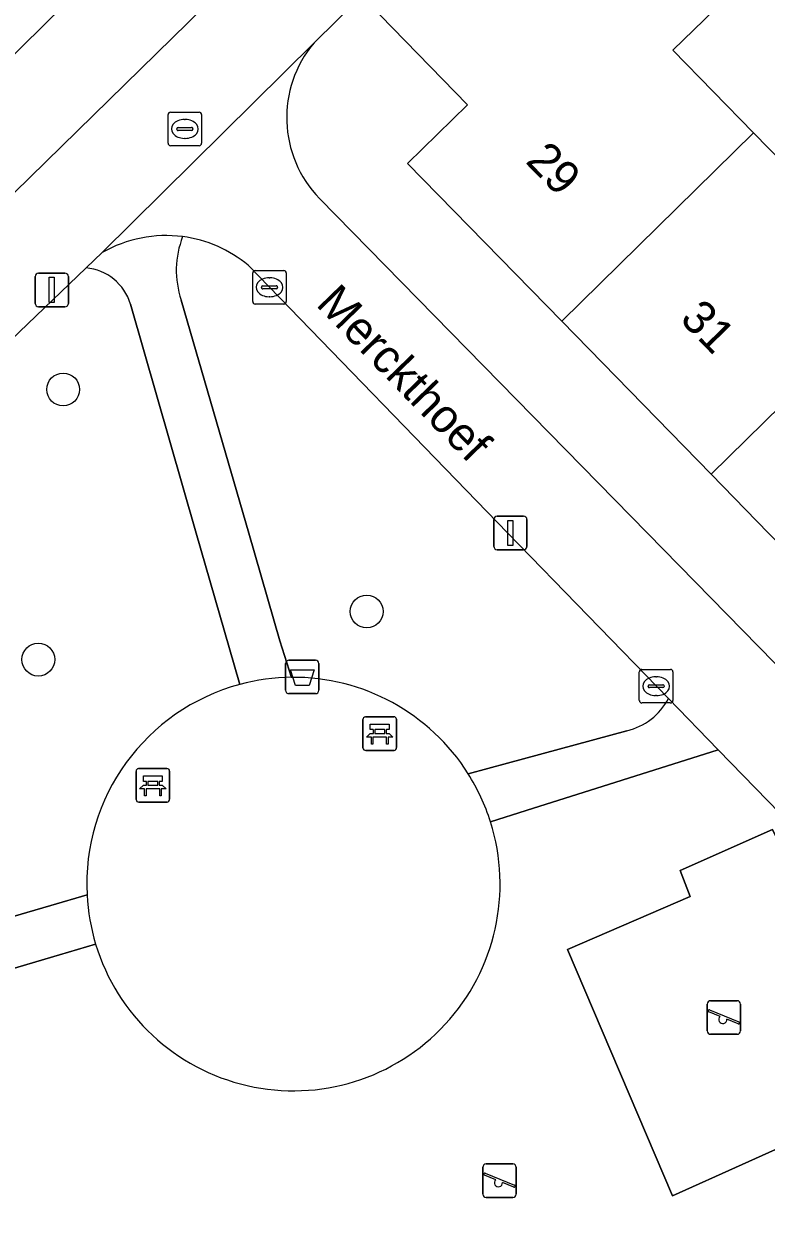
# Model space of a CAD drawing. Extents: x 162879 to 165540, y 384011 to 385181.
# Drawn here: x 164079.05 to 164101.17, y 384229.44 to 384265.17 of the extents above; entities that cross this region are included whole.
import ezdxf

# ---------------------------------------------------------------- set-up
doc = ezdxf.new("R2010")
doc.units = 0
for name, color, linetype in [('IMGEO_Afvalbak', 7, 'Continuous'), ('IMGEO_Bank', 7, 'Continuous'), ('IMGEO_Boom', 7, 'Continuous'), ('IMGEO_Erf', 7, 'Continuous'), ('IMGEO_Groenvoorziening', 7, 'Continuous'), ('IMGEO_Kolk', 7, 'Continuous'), ('IMGEO_Lichtmast', 7, 'Continuous'), ('IMGEO_Openbare_ruimte_label', 7, 'Continuous'), ('IMGEO_Pand', 7, 'Continuous'), ('IMGEO_Pand_nummerreeks', 7, 'Continuous'), ('IMGEO_Rioolput', 7, 'Continuous'), ('IMGEO_Speelvoorziening', 7, 'Continuous'), ('IMGEO_Terreindeel_zand', 7, 'Continuous'), ('IMGEO_Voetpad_halfverhard', 7, 'Continuous'), ('IMGEO_Voetpad_open', 7, 'Continuous')]:
    doc.layers.add(name, color=color, linetype=linetype)

msp = doc.modelspace()

# ---------------------------------------------------------------- linework, layer by layer
at = {"layer": 'IMGEO_Afvalbak'}
for p, q in [((164086.948, 384246.215), (164087.738, 384246.215)), ((164087.738, 384246.215), (164086.948, 384246.215)), ((164086.848, 384245.315), (164086.848, 384246.115)), ((164086.848, 384246.115), (164086.848, 384245.315)), ((164087.838, 384246.115), (164087.838, 384245.315)), ((164087.838, 384245.315), (164087.838, 384246.115)), ((164087.738, 384245.215), (164086.948, 384245.215)), ((164086.948, 384245.215), (164087.738, 384245.215))]:
    msp.add_line(p, q, dxfattribs=at)
msp.add_lwpolyline([(164086.991, 384245.929), (164087.695, 384245.929), (164087.546, 384245.459), (164087.14, 384245.459), (164086.991, 384245.929)], dxfattribs=at)
for centre, start, end in [((164086.948, 384246.115), 90, 180), ((164086.948, 384246.115), 90, 180), ((164087.738, 384246.115), 0, 90), ((164087.738, 384246.115), 360, 90), ((164086.948, 384245.315), 180, 270), ((164086.948, 384245.315), 180, 270), ((164087.738, 384245.315), 270, 0), ((164087.738, 384245.315), 270, 0)]:
    msp.add_arc(centre, 0.1, start, end, dxfattribs=at)
at = {"layer": 'IMGEO_Bank'}
for p, q in [((164089.154, 384243.6), (164089.154, 384244.441)), ((164089.154, 384244.441), (164089.154, 384243.6)), ((164089.229, 384244.525), (164090.07, 384244.525)), ((164090.07, 384244.525), (164089.229, 384244.525)), ((164090.154, 384244.45), (164090.154, 384243.609)), ((164090.154, 384243.609), (164090.154, 384244.45)), ((164089.463, 384244.031), (164089.463, 384244.137)), ((164089.507, 384244.137), (164089.507, 384244.031)), ((164089.795, 384244.143), (164089.513, 384244.143)), ((164089.513, 384244.025), (164089.795, 384244.025)), ((164089.801, 384244.031), (164089.801, 384244.137)), ((164089.845, 384244.137), (164089.845, 384244.031)), ((164089.851, 384243.923), (164089.458, 384243.923)), ((164090.079, 384243.525), (164089.238, 384243.525)), ((164089.238, 384243.525), (164090.079, 384243.525)), ((164082.466, 384242.984), (164083.307, 384242.984)), ((164083.307, 384242.984), (164082.466, 384242.984)), ((164083.391, 384242.909), (164083.391, 384242.068)), ((164083.391, 384242.068), (164083.391, 384242.909)), ((164082.391, 384242.059), (164082.391, 384242.9)), ((164082.391, 384242.9), (164082.391, 384242.059)), ((164082.7, 384242.49), (164082.7, 384242.596)), ((164082.744, 384242.596), (164082.744, 384242.49)), ((164083.032, 384242.602), (164082.75, 384242.602)), ((164083.038, 384242.49), (164083.038, 384242.596)), ((164083.082, 384242.596), (164083.082, 384242.49)), ((164083.088, 384242.382), (164082.695, 384242.382)), ((164082.75, 384242.484), (164083.032, 384242.484)), ((164083.316, 384241.984), (164082.475, 384241.984)), ((164082.475, 384241.984), (164083.316, 384241.984))]:
    msp.add_line(p, q, dxfattribs=at)
for points in [[(164089.401, 384243.923), (164089.259, 384243.923), (164089.371, 384244.025), (164089.457, 384244.025)], [(164089.457, 384244.143), (164089.371, 384244.143), (164089.371, 384244.304), (164089.934, 384244.304), (164089.934, 384244.143), (164089.851, 384244.143)], [(164089.851, 384244.025), (164089.934, 384244.025), (164090.046, 384243.923), (164089.907, 384243.923)], [(164089.451, 384243.916), (164089.451, 384243.709), (164089.408, 384243.709), (164089.408, 384243.916)], [(164089.901, 384243.916), (164089.901, 384243.709), (164089.857, 384243.709), (164089.857, 384243.916)], [(164082.694, 384242.602), (164082.608, 384242.602), (164082.608, 384242.763), (164083.171, 384242.763), (164083.171, 384242.602), (164083.088, 384242.602)], [(164082.638, 384242.382), (164082.496, 384242.382), (164082.608, 384242.484), (164082.694, 384242.484)], [(164082.688, 384242.375), (164082.688, 384242.168), (164082.645, 384242.168), (164082.645, 384242.375)], [(164083.088, 384242.484), (164083.171, 384242.484), (164083.283, 384242.382), (164083.144, 384242.382)], [(164083.138, 384242.375), (164083.138, 384242.168), (164083.094, 384242.168), (164083.094, 384242.375)]]:
    msp.add_lwpolyline(points, dxfattribs=at)
for centre, radius, start, end in [((164089.232, 384244.447), 0.0779, 92.4484, 184.2845), ((164089.232, 384244.447), 0.0779, 92.4484, 184.2845), ((164090.076, 384244.447), 0.0779, 2.4484, 94.2845), ((164090.076, 384244.447), 0.0779, 2.4484, 94.2845), ((164089.456, 384244.136), 0.00671, 2.8957, 87.1043), ((164089.456, 384244.032), 0.00671, 272.8957, 357.1043), ((164089.513, 384244.136), 0.00671, 92.8957, 177.1043), ((164089.513, 384244.032), 0.00671, 182.8957, 267.1043), ((164089.795, 384244.136), 0.00671, 2.8957, 87.1043), ((164089.795, 384244.032), 0.00671, 272.8957, 357.1043), ((164089.852, 384244.136), 0.00671, 92.8957, 177.1043), ((164089.852, 384244.032), 0.00671, 182.8957, 267.1043), ((164089.401, 384243.916), 0.00671, 2.8957, 87.1043), ((164089.458, 384243.916), 0.00671, 92.8957, 177.1043), ((164089.85, 384243.916), 0.00671, 2.8957, 87.1043), ((164089.907, 384243.916), 0.00671, 92.8957, 177.1043), ((164089.232, 384243.603), 0.0779, 182.4484, 274.2845), ((164089.232, 384243.603), 0.0779, 182.4484, 274.2845), ((164090.076, 384243.603), 0.0779, 272.4484, 4.2845), ((164090.076, 384243.603), 0.0779, 272.4484, 4.2845), ((164082.469, 384242.906), 0.0779, 92.4484, 184.2845), ((164082.469, 384242.906), 0.0779, 92.4484, 184.2845), ((164083.313, 384242.906), 0.0779, 2.4484, 94.2845), ((164083.313, 384242.906), 0.0779, 2.4484, 94.2845), ((164082.693, 384242.595), 0.00671, 2.8957, 87.1043), ((164082.75, 384242.595), 0.00671, 92.8957, 177.1043), ((164083.032, 384242.595), 0.00671, 2.8957, 87.1043), ((164083.089, 384242.595), 0.00671, 92.8957, 177.1043), ((164082.638, 384242.375), 0.00671, 2.8957, 87.1043), ((164082.695, 384242.375), 0.00671, 92.8957, 177.1043), ((164082.693, 384242.491), 0.00671, 272.8957, 357.1043), ((164082.75, 384242.491), 0.00671, 182.8957, 267.1043), ((164083.032, 384242.491), 0.00671, 272.8957, 357.1043), ((164083.089, 384242.491), 0.00671, 182.8957, 267.1043), ((164083.087, 384242.375), 0.00671, 2.8957, 87.1043), ((164083.144, 384242.375), 0.00671, 92.8957, 177.1043), ((164082.469, 384242.062), 0.0779, 182.4484, 274.2845), ((164082.469, 384242.062), 0.0779, 182.4484, 274.2845), ((164083.313, 384242.062), 0.0779, 272.4484, 4.2845), ((164083.313, 384242.062), 0.0779, 272.4484, 4.2845)]:
    msp.add_arc(centre, radius, start, end, dxfattribs=at)
at = {"layer": 'IMGEO_Boom'}
for centre in [(164080.215, 384254.279), (164089.265, 384247.663), (164079.475, 384246.23)]:
    msp.add_circle(centre, 0.489, dxfattribs=at)
at = {"layer": 'IMGEO_Erf'}
for points in [[(164128.273, 384286.165), (164127.921, 384285.422), (164125.652, 384280.629), (164118.191, 384284.16), (164113.192, 384279.391), (164113.66, 384278.713), (164111.109, 384276.279), (164107.847, 384279.697), (164105.502, 384282.156), (164087.696, 384264.604)], [(164076.98, 384273.729), (164079.356, 384276.061), (164081.46, 384273.916), (164084.962, 384270.347), (164080.28, 384265.756), (164075.737, 384261.302)], [(164063.201, 384244.93), (164068.383, 384250), (164094.306, 384275.362)], [(164100.566, 384266.508), (164098.393, 384264.385), (164100.798, 384261.923), (164103.04, 384259.629), (164105.211, 384261.75), (164107.42, 384259.489), (164109.189, 384257.679), (164109.774, 384258.25), (164112.3, 384255.666), (164111.316, 384254.701), (164113.746, 384252.214), (164115.964, 384254.382), (164118.137, 384252.139)], [(164119.164, 384235.288), (164114.701, 384239.843), (164110.239, 384244.396), (164105.836, 384248.888), (164104.047, 384247.134), (164101.247, 384250), (164099.531, 384251.756), (164095.078, 384256.314), (164090.485, 384261.015), (164092.274, 384262.763), (164089.297, 384265.81)], [(164087.86, 384259.97), (164097.631, 384250), (164124.609, 384222.474), (164121.025, 384221.682)]]:
    msp.add_lwpolyline(points, dxfattribs=at)
msp.add_arc((164090.322, 384262.377), 3.443, 139.7041, 224.3497, dxfattribs=at)
at = {"layer": 'IMGEO_Groenvoorziening'}
for points in [[(164098.263, 384245.067), (164093.476, 384250), (164085.735, 384257.978)], [(164080.9, 384257.899), (164072.655, 384250), (164068.089, 384245.625), (164065.926, 384243.045), (164066.473, 384242.185), (164074.565, 384238.409)], [(164083.734, 384256.944), (164085.747, 384250), (164086.678, 384246.789), (164087.025, 384245.701)], [(164085.483, 384245.49), (164085.167, 384246.589), (164084.186, 384250), (164082.223, 384256.823)], [(164092.29, 384242.83), (164093.463, 384243.147), (164097.018, 384244.107)], [(164110.095, 384232.91), (164099.747, 384243.542), (164094.021, 384241.732), (164092.956, 384241.395)], [(164076.878, 384238.038), (164079.848, 384238.902), (164080.928, 384239.216)], [(164081.185, 384237.751), (164080.109, 384237.434), (164077.341, 384236.617)]]:
    msp.add_lwpolyline(points, dxfattribs=at)
msp.add_lwpolyline([(164095.246, 384237.595), (164098.907, 384239.168), (164098.613, 384239.942), (164101.359, 384241.171), (164102.299, 384239.25), (164101.997, 384239.11), (164104.613, 384233.049), (164098.376, 384230.254)], close=True, dxfattribs=at)
for centre, radius, start, end in [((164086.357, 384257.827), 2.768, 158.7179, 198.612), ((164083.283, 384255.029), 3.835, 50.261, 82.5878), ((164080.771, 384256.389), 1.515, 16.632, 85.1249), ((164087.082, 384239.539), 6.162, 105.0356, 183.0042), ((164087.079, 384239.537), 6.164, 32.2903, 90.5025), ((164096.568, 384245.978), 1.924, 283.5195, 331.751), ((164087.08, 384239.542), 6.161, 196.896, 17.5063)]:
    msp.add_arc(centre, radius, start, end, dxfattribs=at)
at = {"layer": 'IMGEO_Kolk'}
for p, q in [((164085.867, 384256.897), (164085.867, 384257.749)), ((164085.942, 384257.823), (164086.794, 384257.823)), ((164086.355, 384257.603), (164086.38, 384257.603)), ((164086.868, 384257.749), (164086.868, 384256.897)), ((164086.126, 384257.317), (164086.126, 384257.329)), ((164086.564, 384257.28), (164086.166, 384257.28)), ((164086.169, 384257.366), (164086.567, 384257.366)), ((164086.61, 384257.329), (164086.61, 384257.317)), ((164086.378, 384257.043), (164086.353, 384257.043)), ((164086.794, 384256.823), (164085.942, 384256.823)), ((164097.392, 384245.011), (164097.392, 384245.863)), ((164097.467, 384245.937), (164098.319, 384245.937)), ((164098.393, 384245.863), (164098.393, 384245.011)), ((164097.651, 384245.431), (164097.651, 384245.443)), ((164097.694, 384245.48), (164098.092, 384245.48)), ((164097.88, 384245.717), (164097.905, 384245.717)), ((164098.135, 384245.443), (164098.135, 384245.431)), ((164098.089, 384245.394), (164097.691, 384245.394)), ((164097.903, 384245.157), (164097.878, 384245.157)), ((164098.319, 384244.937), (164097.467, 384244.937))]:
    msp.add_line(p, q, dxfattribs=at)
for points in [[(164085.867, 384256.897), (164085.867, 384257.749)], [(164085.942, 384257.823), (164086.794, 384257.823)], [(164086.868, 384257.749), (164086.868, 384256.897)], [(164086.794, 384256.823), (164085.942, 384256.823)], [(164097.392, 384245.011), (164097.392, 384245.863)], [(164097.467, 384245.937), (164098.319, 384245.937)], [(164098.393, 384245.863), (164098.393, 384245.011)], [(164098.319, 384244.937), (164097.467, 384244.937)]]:
    msp.add_lwpolyline(points, dxfattribs=at)
for centre, radius, start, end in [((164085.944, 384257.747), 0.0765, 91.552, 178.448), ((164085.944, 384257.747), 0.0765, 91.552, 178.448), ((164086.792, 384257.747), 0.0765, 1.552, 88.448), ((164086.792, 384257.747), 0.0765, 1.552, 88.448), ((164086.166, 384257.326), 0.0403, 85.8775, 175.7526), ((164086.163, 384257.316), 0.0366, 178.938, 274.7102), ((164086.567, 384257.323), 0.043, 264.8664, 352.4533), ((164086.571, 384257.328), 0.0386, 1.7309, 96.639), ((164085.944, 384256.899), 0.0765, 181.552, 268.448), ((164085.944, 384256.899), 0.0765, 181.552, 268.448), ((164086.792, 384256.899), 0.0765, 271.552, 358.448), ((164086.792, 384256.899), 0.0765, 271.552, 358.448), ((164097.469, 384245.861), 0.0765, 91.552, 178.448), ((164097.469, 384245.861), 0.0765, 91.552, 178.448), ((164098.317, 384245.861), 0.0765, 1.552, 88.448), ((164098.317, 384245.861), 0.0765, 1.552, 88.448), ((164097.691, 384245.44), 0.0403, 85.8775, 175.7526), ((164097.688, 384245.43), 0.0366, 178.938, 274.7102), ((164098.092, 384245.437), 0.043, 264.8664, 352.4533), ((164098.096, 384245.442), 0.0386, 1.7309, 96.639), ((164097.469, 384245.013), 0.0765, 181.552, 268.448), ((164097.469, 384245.013), 0.0765, 181.552, 268.448), ((164098.317, 384245.013), 0.0765, 271.552, 358.448), ((164098.317, 384245.013), 0.0765, 271.552, 358.448)]:
    msp.add_arc(centre, radius, start, end, dxfattribs=at)
for centre, major_axis, ratio, start_param, end_param in [((164086.354, 384257.323), (-0.387, 0.002), 0.722429, 4.712389, 7.853982), ((164086.379, 384257.323), (-0.39, 0.002), 0.717154, 1.570796, 4.712389), ((164097.879, 384245.437), (-0.387, 0.002), 0.722429, 4.712389, 7.853982), ((164097.904, 384245.437), (-0.39, 0.002), 0.717154, 1.570796, 4.712389)]:
    msp.add_ellipse(centre, major_axis=major_axis, ratio=ratio, start_param=start_param, end_param=end_param, dxfattribs=at)
at = {"layer": 'IMGEO_Lichtmast'}
for p, q in [((164079.381, 384256.845), (164079.381, 384257.645)), ((164079.381, 384257.645), (164079.381, 384256.845)), ((164079.481, 384257.745), (164080.271, 384257.745)), ((164080.271, 384257.745), (164079.481, 384257.745)), ((164080.371, 384257.645), (164080.371, 384256.845)), ((164080.371, 384256.845), (164080.371, 384257.645)), ((164080.271, 384256.745), (164079.481, 384256.745)), ((164079.481, 384256.745), (164080.271, 384256.745)), ((164093.153, 384250.504), (164093.943, 384250.504)), ((164093.943, 384250.504), (164093.153, 384250.504)), ((164093.053, 384249.604), (164093.053, 384250.404)), ((164093.053, 384250.404), (164093.053, 384249.604)), ((164094.043, 384250.404), (164094.043, 384249.604)), ((164094.043, 384249.604), (164094.043, 384250.404)), ((164093.943, 384249.504), (164093.153, 384249.504)), ((164093.153, 384249.504), (164093.943, 384249.504))]:
    msp.add_line(p, q, dxfattribs=at)
for points in [[(164079.801, 384257.62), (164079.951, 384257.62), (164079.951, 384256.87), (164079.801, 384256.87), (164079.801, 384257.62)], [(164093.473, 384250.379), (164093.623, 384250.379), (164093.623, 384249.629), (164093.473, 384249.629), (164093.473, 384250.379)]]:
    msp.add_lwpolyline(points, dxfattribs=at)
for centre, start, end in [((164079.481, 384257.645), 90, 180), ((164079.481, 384257.645), 90, 180), ((164080.271, 384257.645), 0, 90), ((164080.271, 384257.645), 360, 90), ((164079.481, 384256.845), 180, 270), ((164079.481, 384256.845), 180, 270), ((164080.271, 384256.845), 270, 0), ((164080.271, 384256.845), 270, 0), ((164093.153, 384250.404), 90, 180), ((164093.153, 384250.404), 90, 180), ((164093.943, 384250.404), 0, 90), ((164093.943, 384250.404), 360, 90), ((164093.153, 384249.604), 180, 270), ((164093.153, 384249.604), 180, 270), ((164093.943, 384249.604), 270, 0), ((164093.943, 384249.604), 270, 0)]:
    msp.add_arc(centre, 0.1, start, end, dxfattribs=at)
at = {"layer": 'IMGEO_Pand'}
for points in [[(164080.28, 384265.756), (164072.57, 384273.616), (164070.503, 384271.588), (164072.57, 384269.481), (164070.096, 384267.053), (164075.737, 384261.302)], [(164095.078, 384256.314), (164100.798, 384261.923), (164098.393, 384264.385), (164100.566, 384266.508), (164098.387, 384268.737), (164097.009, 384267.39), (164094.032, 384270.437), (164089.297, 384265.81), (164092.274, 384262.763), (164090.485, 384261.015)], [(164107.42, 384259.489), (164105.211, 384261.75), (164103.04, 384259.629), (164100.798, 384261.923), (164095.078, 384256.314), (164099.531, 384251.756)], [(164111.316, 384254.701), (164112.3, 384255.666), (164109.774, 384258.25), (164109.189, 384257.679), (164107.42, 384259.489), (164099.531, 384251.756), (164101.247, 384250), (164104.047, 384247.134), (164105.836, 384248.888), (164109.574, 384252.993)]]:
    msp.add_lwpolyline(points, close=True, dxfattribs=at)
at = {"layer": 'IMGEO_Rioolput'}
for p, q in [((164083.343, 384261.615), (164083.343, 384262.467)), ((164083.418, 384262.541), (164084.27, 384262.541)), ((164083.831, 384262.321), (164083.856, 384262.321)), ((164084.344, 384262.467), (164084.344, 384261.615)), ((164083.602, 384262.035), (164083.602, 384262.047)), ((164084.04, 384261.998), (164083.642, 384261.998)), ((164083.645, 384262.084), (164084.043, 384262.084)), ((164084.086, 384262.047), (164084.086, 384262.035)), ((164084.27, 384261.541), (164083.418, 384261.541)), ((164083.854, 384261.761), (164083.829, 384261.761))]:
    msp.add_line(p, q, dxfattribs=at)
for points in [[(164083.343, 384261.615), (164083.343, 384262.467)], [(164083.418, 384262.541), (164084.27, 384262.541)], [(164084.344, 384262.467), (164084.344, 384261.615)], [(164084.27, 384261.541), (164083.418, 384261.541)]]:
    msp.add_lwpolyline(points, dxfattribs=at)
for centre, radius, start, end in [((164083.42, 384262.465), 0.0765, 91.552, 178.448), ((164083.42, 384262.465), 0.0765, 91.552, 178.448), ((164084.268, 384262.465), 0.0765, 1.552, 88.448), ((164084.268, 384262.465), 0.0765, 1.552, 88.448), ((164083.642, 384262.044), 0.0403, 85.8775, 175.7526), ((164083.639, 384262.034), 0.0366, 178.938, 274.7102), ((164084.043, 384262.041), 0.043, 264.8664, 352.4533), ((164084.047, 384262.046), 0.0386, 1.7309, 96.639), ((164083.42, 384261.617), 0.0765, 181.552, 268.448), ((164083.42, 384261.617), 0.0765, 181.552, 268.448), ((164084.268, 384261.617), 0.0765, 271.552, 358.448), ((164084.268, 384261.617), 0.0765, 271.552, 358.448)]:
    msp.add_arc(centre, radius, start, end, dxfattribs=at)
for centre, major_axis, ratio, start_param, end_param in [((164083.83, 384262.041), (-0.387, 0.002), 0.722429, 4.712389, 7.853982), ((164083.855, 384262.041), (-0.39, 0.002), 0.717154, 1.570796, 4.712389)]:
    msp.add_ellipse(centre, major_axis=major_axis, ratio=ratio, start_param=start_param, end_param=end_param, dxfattribs=at)
at = {"layer": 'IMGEO_Speelvoorziening'}
for p, q in [((164099.418, 384235.166), (164099.418, 384235.966)), ((164099.418, 384235.966), (164099.418, 384235.166)), ((164099.487, 384235.791), (164100.363, 384235.438)), ((164099.518, 384236.066), (164100.308, 384236.066)), ((164100.308, 384236.066), (164099.518, 384236.066)), ((164100.408, 384235.966), (164100.408, 384235.166)), ((164100.408, 384235.166), (164100.408, 384235.966)), ((164099.801, 384235.594), (164099.462, 384235.731)), ((164100.339, 384235.378), (164099.999, 384235.515)), ((164100.308, 384235.066), (164099.518, 384235.066)), ((164099.518, 384235.066), (164100.308, 384235.066)), ((164092.829, 384231.202), (164093.619, 384231.202)), ((164093.619, 384231.202), (164092.829, 384231.202)), ((164092.729, 384230.302), (164092.729, 384231.102)), ((164092.729, 384231.102), (164092.729, 384230.302)), ((164093.112, 384230.73), (164092.773, 384230.867)), ((164092.798, 384230.927), (164093.674, 384230.574)), ((164093.719, 384231.102), (164093.719, 384230.302)), ((164093.719, 384230.302), (164093.719, 384231.102)), ((164093.65, 384230.514), (164093.31, 384230.651)), ((164093.619, 384230.202), (164092.829, 384230.202)), ((164092.829, 384230.202), (164093.619, 384230.202))]:
    msp.add_line(p, q, dxfattribs=at)
for centre, radius, start, end in [((164099.518, 384235.966), 0.1, 90, 180), ((164099.518, 384235.966), 0.1, 90, 180), ((164099.475, 384235.761), 0.0327, 68.078, 248.078), ((164100.308, 384235.966), 0.1, 0, 90), ((164100.308, 384235.966), 0.1, 360, 90), ((164099.88, 384235.504), 0.12, 130.9928, 5.1632), ((164100.351, 384235.408), 0.0327, 248.078, 68.078), ((164099.518, 384235.166), 0.1, 180, 270), ((164099.518, 384235.166), 0.1, 180, 270), ((164100.308, 384235.166), 0.1, 270, 0), ((164100.308, 384235.166), 0.1, 270, 0), ((164092.829, 384231.102), 0.1, 90, 180), ((164092.829, 384231.102), 0.1, 90, 180), ((164093.619, 384231.102), 0.1, 0, 90), ((164093.619, 384231.102), 0.1, 360, 90), ((164092.786, 384230.897), 0.0327, 68.078, 248.078), ((164093.191, 384230.64), 0.12, 130.9928, 5.1632), ((164093.662, 384230.544), 0.0327, 248.078, 68.078), ((164092.829, 384230.302), 0.1, 180, 270), ((164092.829, 384230.302), 0.1, 180, 270), ((164093.619, 384230.302), 0.1, 270, 0), ((164093.619, 384230.302), 0.1, 270, 0)]:
    msp.add_arc(centre, radius, start, end, dxfattribs=at)
at = {"layer": 'IMGEO_Terreindeel_zand'}
msp.add_lwpolyline([(164104.613, 384233.049), (164101.997, 384239.11), (164102.299, 384239.25), (164101.359, 384241.171), (164098.613, 384239.942), (164098.907, 384239.168), (164095.246, 384237.595), (164098.376, 384230.254)], close=True, dxfattribs=at)
at = {"layer": 'IMGEO_Voetpad_halfverhard'}
for points in [[(164081.379, 384258.358), (164080.9, 384257.899)], [(164087.025, 384245.701), (164086.678, 384246.789), (164085.747, 384250), (164083.734, 384256.944)], [(164082.223, 384256.823), (164084.186, 384250), (164085.167, 384246.589), (164085.483, 384245.49)], [(164092.956, 384241.395), (164094.021, 384241.732), (164099.747, 384243.542), (164098.263, 384245.067)], [(164097.018, 384244.107), (164093.463, 384243.147), (164092.29, 384242.83)], [(164080.928, 384239.216), (164079.848, 384238.902), (164076.878, 384238.038)], [(164077.341, 384236.617), (164080.109, 384237.434), (164081.185, 384237.751)]]:
    msp.add_lwpolyline(points, dxfattribs=at)
for centre, radius, start, end in [((164083.281, 384255.04), 3.824, 82.5307, 119.8226), ((164086.357, 384257.827), 2.768, 158.7179, 198.612), ((164080.771, 384256.389), 1.515, 16.632, 85.1249), ((164087.088, 384239.498), 6.204, 90.5855, 104.9979), ((164096.568, 384245.978), 1.924, 283.5195, 331.751), ((164087.057, 384239.529), 6.187, 17.5508, 32.2423), ((164087.07, 384239.538), 6.151, 183.0051, 196.8948)]:
    msp.add_arc(centre, radius, start, end, dxfattribs=at)
at = {"layer": 'IMGEO_Voetpad_open'}
for points in [[(164070.594, 384214.118), (164065.064, 384240.618), (164064.991, 384240.969), (164065.316, 384242.317), (164065.926, 384243.045), (164068.089, 384245.625), (164072.655, 384250), (164080.9, 384257.899), (164081.379, 384258.358), (164087.696, 384264.604), (164105.502, 384282.156)], [(164094.306, 384275.362), (164068.383, 384250), (164063.201, 384244.93), (164061.9, 384242.942), (164062.005, 384240.357), (164067.56, 384213.721)], [(164087.696, 384264.604), (164081.379, 384258.358)], [(164121.025, 384221.682), (164124.609, 384222.474), (164097.631, 384250), (164087.86, 384259.97)], [(164085.735, 384257.978), (164093.476, 384250), (164098.263, 384245.067), (164099.747, 384243.542), (164110.095, 384232.91)]]:
    msp.add_lwpolyline(points, dxfattribs=at)
for centre, radius, start, end in [((164090.322, 384262.377), 3.443, 139.7041, 224.3497), ((164083.281, 384255.04), 3.824, 82.5307, 119.8226), ((164083.283, 384255.029), 3.835, 50.261, 82.5878), ((164087.082, 384239.539), 6.162, 105.0356, 183.0042), ((164087.088, 384239.498), 6.204, 90.5855, 104.9979), ((164087.079, 384239.537), 6.164, 32.2903, 90.5025), ((164087.057, 384239.529), 6.187, 17.5508, 32.2423), ((164087.08, 384239.542), 6.161, 196.896, 17.5063), ((164087.07, 384239.538), 6.151, 183.0051, 196.8948)]:
    msp.add_arc(centre, radius, start, end, dxfattribs=at)

# ---------------------------------------------------------------- texts
at = {"layer": 'IMGEO_Openbare_ruimte_label'}
msp.add_text('Merckthoef', height=1, rotation=314.1086, dxfattribs=at).set_placement((164087.724, 384256.798))
at = {"layer": 'IMGEO_Pand_nummerreeks'}
for s, p in [('29', (164093.97, 384261.053)), ('31', (164098.569, 384256.346))]:
    msp.add_text(s, height=1, rotation=314.334, dxfattribs=at).set_placement(p)

doc.saveas('drawing.dxf')
